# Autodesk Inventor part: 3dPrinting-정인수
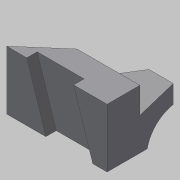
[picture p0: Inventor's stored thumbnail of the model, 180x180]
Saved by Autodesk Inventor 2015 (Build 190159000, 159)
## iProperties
Created: 2015-05
Part Number: 3dPrinting-정인수
Material: 일반
Document SubType Name: Modeling
Designer: Insu
Density: 1 g/cm^3
Appearance: 기본값
Author: Insu
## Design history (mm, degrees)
sketch "스케치1"
  geometry: L1 (-67.5, -44.5)-(67.5, -44.5); L2 (67.5, -44.5)-(67.5, 44.5); L3 (67.5, 44.5)-(-67.5, 44.5); L4 (-67.5, 44.5)-(-67.5, -44.5); L5 (-67.5, -44.5)-(67.5, 44.5); L6 (67.5, -44.5)-(-67.5, 44.5); L7 (-67.5, -44.5)-(34.883, 44.5); 1 further point
  constraints: 14 end point, 2 midpoint, 2 parallel, 1 horizontal, 1 perpendicular, 1 point on line
  dimensions: "d0" = 135 distance of L3.end L2.end; "d1" = 89 distance of L2.end L1.end; "d2" = 139 deg angle of L7 L1
extrude "돌출1" new body sketch "스케치1" stored distance "d3" = 79; taper "d4" = 0 deg
sketch "스케치2"
  geometry: L1 (79, 89)-(79, 0) reference; L2 (79, 89)-(0, 89) reference; C1 r 44 at (88, 97); 1 further point
  constraints: 1 centre point
  dimensions: "d5" = 9 distance from line of L1 C1.centre; "d6" = 8 distance from line of C1.centre L2; "d7" = 44 radius of C1
extrude "돌출2" cut sketch "스케치2" stored distance "d8" = 0; taper "d9" = 0 deg
sketch "스케치3"
  geometry: L1 (44.733, 89)-(0, 89) reference; L2 (0, 0)-(0, 89) reference; L3 (0, 44)-(35, 44); L4 (35, 44)-(20.379, 89); L5 (79, 0)-(0, 0) reference; 1 further point
  constraints: 4 end point, 2 point on line, 1 horizontal
  dimensions: "d10" = 44 distance between parallel lines of L5 L3; "d11" = 72 deg angle of L4 L3; "d12" = 35 distance of L3.start L3.end
extrude "돌출3" cut sketch "스케치3" stored distance "d13" = 79; taper "d14" = 0 deg
sketch "스케치4"
  geometry: L1 (0, 0)-(135, 0) reference; L2 (135, -79)-(0, -79) reference; L3 (27, 0)-(52.669, -79); L4 (0, -79)-(62.04, -79) reference; L5 (90.088, 0)-(115.756, -79); L6 (0, 0)-(0, -79) reference; 1 further point
  constraints: 4 end point, 4 point on line, 1 parallel
  dimensions: "d15" = 27 distance from line of L3.start L6; "d16" = 72 deg angle of L2 L5; "d17" = 60 distance between parallel lines of L3 L5
extrude "돌출4" cut sketch "스케치4" distance "d18" = 14; taper "d19" = 0 deg
node "솔리드1"
